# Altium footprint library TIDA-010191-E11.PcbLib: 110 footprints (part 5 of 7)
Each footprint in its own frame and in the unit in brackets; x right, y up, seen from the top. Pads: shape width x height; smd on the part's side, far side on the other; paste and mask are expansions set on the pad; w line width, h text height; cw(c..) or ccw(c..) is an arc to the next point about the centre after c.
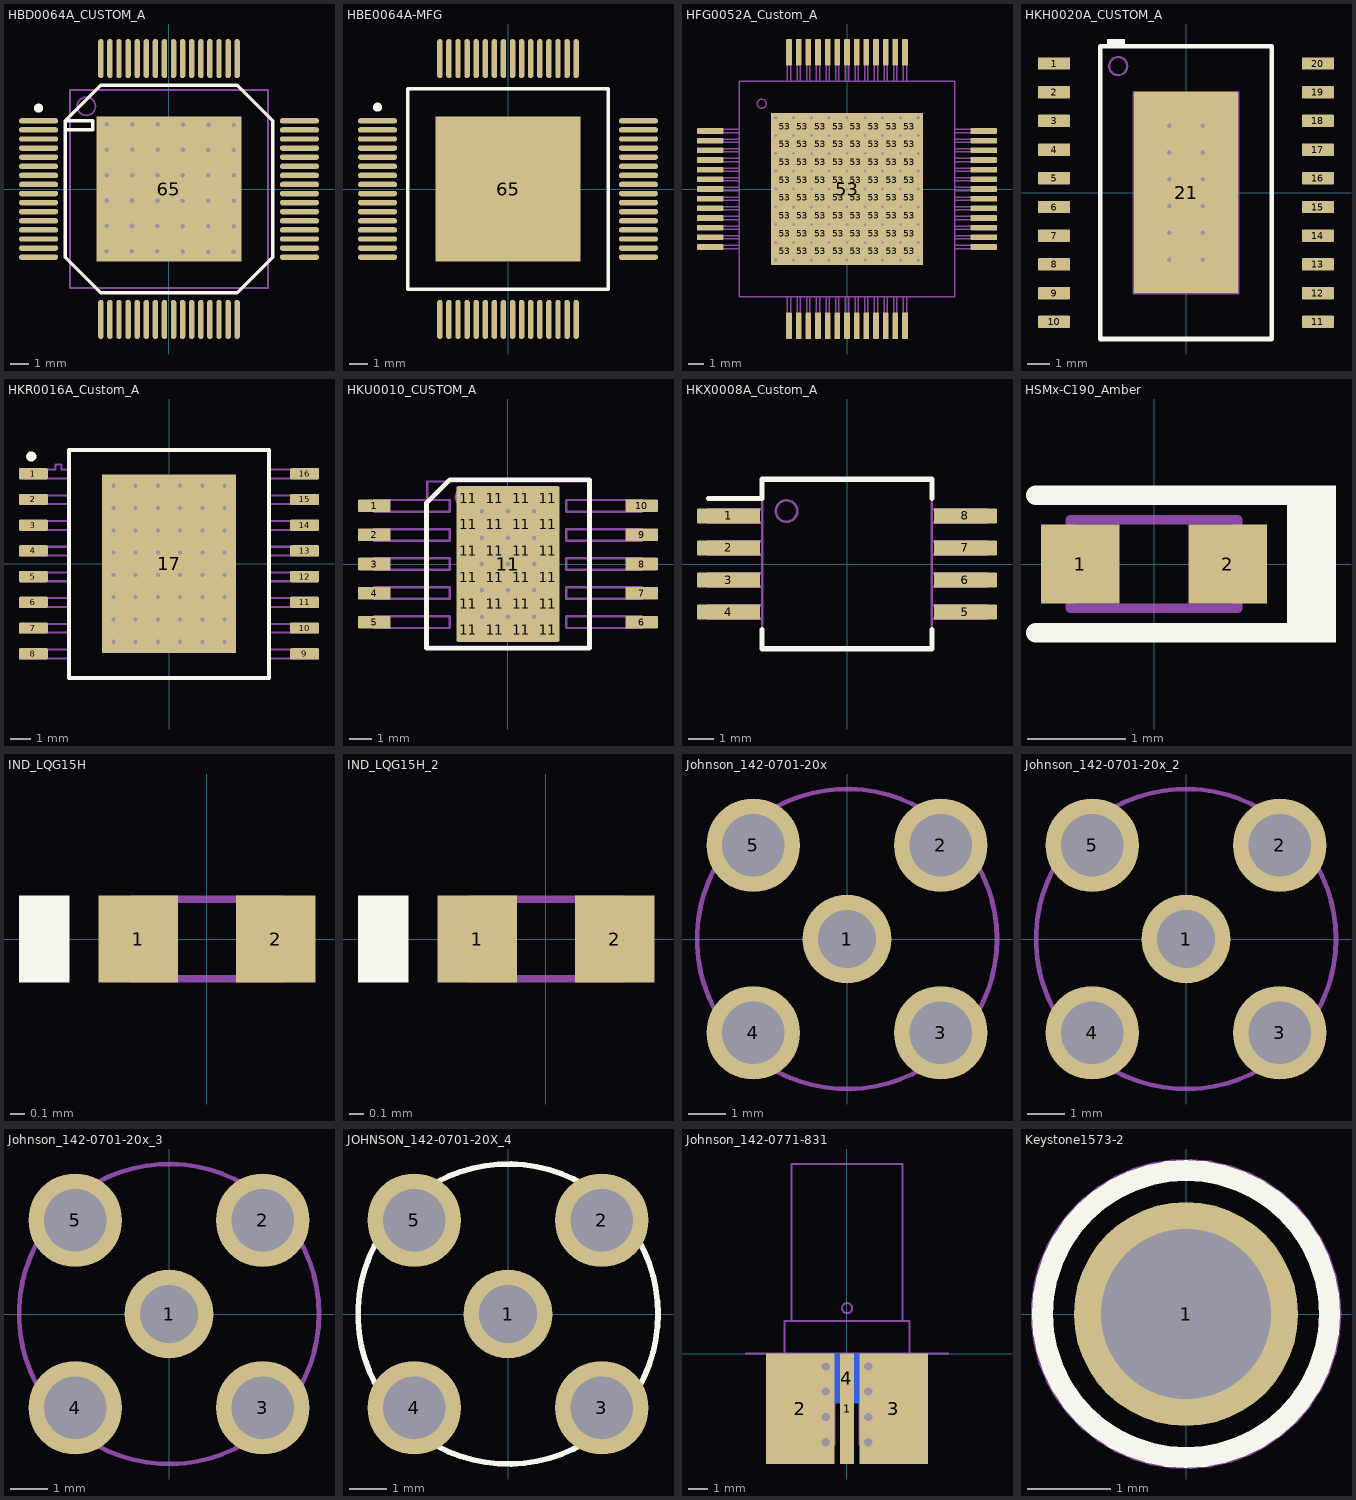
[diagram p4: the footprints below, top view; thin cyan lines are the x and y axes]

## HBD0064A_CUSTOM_A [mm] "CFP, 64-Leads, Body 10.9x10.9mm, Pitch 0.5 mm"
height 2.31
pads (65):
  rrect100% 2.15x0.3 smd: 1(-7.175,3.75) 2(-7.175,3.25) 3(-7.175,2.75) 4(-7.175,2.25) 5(-7.175,1.75) 6(-7.175,1.25) 7(-7.175,0.75) 8(-7.175,0.25) 9(-7.175,-0.25) 10(-7.175,-0.75) 11(-7.175,-1.25) 12(-7.175,-1.75) 13(-7.175,-2.25) 14(-7.175,-2.75) 15(-7.175,-3.25) 16(-7.175,-3.75) 33(7.175,-3.75) 34(7.175,-3.25) 35(7.175,-2.75) 36(7.175,-2.25) 37(7.175,-1.75) 38(7.175,-1.25) 39(7.175,-0.75) 40(7.175,-0.25) 41(7.175,0.25) 42(7.175,0.75) 43(7.175,1.25) 44(7.175,1.75) 45(7.175,2.25) 46(7.175,2.75) 47(7.175,3.25) 48(7.175,3.75)
  rrect100% 0.3x2.15 smd: 17(-3.75,-7.175) 18(-3.25,-7.175) 19(-2.75,-7.175) 20(-2.25,-7.175) 21(-1.75,-7.175) 22(-1.25,-7.175) 23(-0.75,-7.175) 24(-0.25,-7.175) 25(0.25,-7.175) 26(0.75,-7.175) 27(1.25,-7.175) 28(1.75,-7.175) 29(2.25,-7.175) 30(2.75,-7.175) 31(3.25,-7.175) 32(3.75,-7.175) 49(3.75,7.175) 50(3.25,7.175) 51(2.75,7.175) 52(2.25,7.175) 53(1.75,7.175) 54(1.25,7.175) 55(0.75,7.175) 56(0.25,7.175) 57(-0.25,7.175) 58(-0.75,7.175) 59(-1.25,7.175) 60(-1.75,7.175) 61(-2.25,7.175) 62(-2.75,7.175) 63(-3.25,7.175) 64(-3.75,7.175)
  rrect1% 8x8 smd: 65(0,0)
via -3.417,3.56 diameter 0.508 hole 0.254
via -2.02,3.556 diameter 0.508 hole 0.254
via -0.623,3.552 diameter 0.508 hole 0.254
via 0.774,3.548 diameter 0.508 hole 0.254
via 2.171,3.544 diameter 0.508 hole 0.254
via 3.568,3.54 diameter 0.508 hole 0.254
via 3.56,0.746 diameter 0.508 hole 0.254
via 3.564,2.143 diameter 0.508 hole 0.254
via 3.552,-2.048 diameter 0.508 hole 0.254
via 3.548,-3.445 diameter 0.508 hole 0.254
via 2.163,0.75 diameter 0.508 hole 0.254
via 2.167,2.147 diameter 0.508 hole 0.254
via 2.155,-2.044 diameter 0.508 hole 0.254
via 2.151,-3.441 diameter 0.508 hole 0.254
via 0.766,0.754 diameter 0.508 hole 0.254
via 0.77,2.151 diameter 0.508 hole 0.254
via 0.758,-2.04 diameter 0.508 hole 0.254
via 0.754,-3.437 diameter 0.508 hole 0.254
via -0.631,0.758 diameter 0.508 hole 0.254
via -0.627,2.155 diameter 0.508 hole 0.254
via -0.639,-2.036 diameter 0.508 hole 0.254
via -0.643,-3.433 diameter 0.508 hole 0.254
via -2.028,0.762 diameter 0.508 hole 0.254
via -2.024,2.159 diameter 0.508 hole 0.254
via -2.036,-2.032 diameter 0.508 hole 0.254
via -2.04,-3.429 diameter 0.508 hole 0.254
via -3.437,-3.425 diameter 0.508 hole 0.254
via -3.433,-2.028 diameter 0.508 hole 0.254
via -3.421,2.163 diameter 0.508 hole 0.254
via -3.425,0.766 diameter 0.508 hole 0.254
via 3.556,-0.651 diameter 0.508 hole 0.254
via 2.159,-0.647 diameter 0.508 hole 0.254
via 0.762,-0.643 diameter 0.508 hole 0.254
via -3.429,-0.631 diameter 0.508 hole 0.254
via -2.032,-0.635 diameter 0.508 hole 0.254
via -0.635,-0.639 diameter 0.508 hole 0.254
Top Overlay:
  circle w0.25: c-7.175,4.45 r0.125
  lines w0.2: -5.7,3.25 -4.2,3.25 -4.2,3.75 -5.7,3.75 ; -5.7,3.75 -5.7,-3.75 -3.75,-5.7 3.75,-5.7 5.7,-3.75 5.7,3.75 3.75,5.7 -3.75,5.7 -5.7,3.75
Mechanical 5:
  circle w0.1: c-4.55,4.55 r0.5
  lines w0.1: -5.45,-5.45 -5.45,5.45 5.45,5.45 5.45,-5.45 -5.45,-5.45
  text ".Designator" at -2,-0.7 h1.85
3D body "CQFP50P1560X1560X231-64N.step": height 2.31, standoff 0, extent -7.865,-7.865 7.865,7.865

## HBE0064A-MFG [mm]
pads (65):
  rrect100% 2.15x0.3 smd paste+0 mask+0: 1(-7.175,3.75) 2(-7.175,3.25) 3(-7.175,2.75) 4(-7.175,2.25) 5(-7.175,1.75) 6(-7.175,1.25) 7(-7.175,0.75) 8(-7.175,0.25) 9(-7.175,-0.25) 10(-7.175,-0.75) 11(-7.175,-1.25) 12(-7.175,-1.75) 13(-7.175,-2.25) 14(-7.175,-2.75) 15(-7.175,-3.25) 16(-7.175,-3.75) 33(7.175,-3.75) 34(7.175,-3.25) 35(7.175,-2.75) 36(7.175,-2.25) 37(7.175,-1.75) 38(7.175,-1.25) 39(7.175,-0.75) 40(7.175,-0.25) 41(7.175,0.25) 42(7.175,0.75) 43(7.175,1.25) 44(7.175,1.75) 45(7.175,2.25) 46(7.175,2.75) 47(7.175,3.25) 48(7.175,3.75)
  rrect100% 0.3x2.15 smd paste+0 mask+0: 17(-3.75,-7.175) 18(-3.25,-7.175) 19(-2.75,-7.175) 20(-2.25,-7.175) 21(-1.75,-7.175) 22(-1.25,-7.175) 23(-0.75,-7.175) 24(-0.25,-7.175) 25(0.25,-7.175) 26(0.75,-7.175) 27(1.25,-7.175) 28(1.75,-7.175) 29(2.25,-7.175) 30(2.75,-7.175) 31(3.25,-7.175) 32(3.75,-7.175) 49(3.75,7.175) 50(3.25,7.175) 51(2.75,7.175) 52(2.25,7.175) 53(1.75,7.175) 54(1.25,7.175) 55(0.75,7.175) 56(0.25,7.175) 57(-0.25,7.175) 58(-0.75,7.175) 59(-1.25,7.175) 60(-1.75,7.175) 61(-2.25,7.175) 62(-2.75,7.175) 63(-3.25,7.175) 64(-3.75,7.175)
  rrect1% 8x8 smd paste+0 mask+0: 65(0,0)
Top Overlay:
  circle w0.25: c-7.175,4.5 r0.125
  lines w0.2: -5.515,-5.515 5.515,-5.515 5.515,5.515 -5.515,5.515 -5.515,-5.515
Mechanical 5:
  lines w0.1: -5.515,-5.515 5.515,-5.515 5.515,5.515 -5.515,5.515 -5.515,-5.515
  text ".Designator" at 0,0 h0.5
3D body "IC_LMK04832W-MLS_CFP64.STEP": height 0.25, standoff 0, extent -8.35,-8.35 8.35,8.35

## HFG0052A_Custom_A [mm] "CFP-52"
height 2.68
pads (117):
  rrect26% 1.727x0.381 smd: 1(-8.992,3.81) 2(-8.992,3.175) 3(-8.992,2.54) 4(-8.992,1.905) 5(-8.992,1.27) 6(-8.992,0.635) 7(-8.992,0) 8(-8.992,-0.635) 9(-8.992,-1.27) 10(-8.992,-1.905) 11(-8.992,-2.54) 12(-8.992,-3.175) 13(-8.992,-3.81) 27(8.992,-3.81) 28(8.992,-3.175) 29(8.992,-2.54) 30(8.992,-1.905) 31(8.992,-1.27) 32(8.992,-0.635) 33(8.992,0) 34(8.992,0.635) 35(8.992,1.27) 36(8.992,1.905) 37(8.992,2.54) 38(8.992,3.175) 39(8.992,3.81)
  rrect26% 0.381x1.727 smd: 14(-3.81,-8.992) 15(-3.175,-8.992) 16(-2.54,-8.992) 17(-1.905,-8.992) 18(-1.27,-8.992) 19(-0.635,-8.992) 20(0,-8.992) 21(0.635,-8.992) 22(1.27,-8.992) 23(1.905,-8.992) 24(2.54,-8.992) 25(3.175,-8.992) 26(3.81,-8.992) 40(3.81,8.992) 41(3.175,8.992) 42(2.54,8.992) 43(1.905,8.992) 44(1.27,8.992) 45(0.635,8.992) 46(0,8.992) 47(-0.635,8.992) 48(-1.27,8.992) 49(-1.905,8.992) 50(-2.54,8.992) 51(-3.175,8.992) 52(-3.81,8.992)
  rrect50% 0.97x0.97 on Top Paste: 53(-4.095,-4.095) 53(-4.095,-2.925) 53(-4.095,-1.755) 53(-4.095,-0.585) 53(-4.095,0.585) 53(-4.095,1.755) 53(-4.095,2.925) 53(-4.095,4.095) 53(-2.925,-4.095) 53(-2.925,-2.925) 53(-2.925,-1.755) 53(-2.925,-0.585) 53(-2.925,0.585) 53(-2.925,1.755) 53(-2.925,2.925) 53(-2.925,4.095) 53(-1.755,-4.095) 53(-1.755,-2.925) 53(-1.755,-1.755) 53(-1.755,-0.585) 53(-1.755,0.585) 53(-1.755,1.755) 53(-1.755,2.925) 53(-1.755,4.095) 53(-0.585,-4.095) 53(-0.585,-2.925) 53(-0.585,-1.755) 53(-0.585,-0.585) 53(-0.585,0.585) 53(-0.585,1.755) 53(-0.585,2.925) 53(-0.585,4.095) 53(0.585,-4.095) 53(0.585,-2.925) 53(0.585,-1.755) 53(0.585,-0.585) 53(0.585,0.585) 53(0.585,1.755) 53(0.585,2.925) 53(0.585,4.095) 53(1.755,-4.095) 53(1.755,-2.925) 53(1.755,-1.755) 53(1.755,-0.585) 53(1.755,0.585) 53(1.755,1.755) 53(1.755,2.925) 53(1.755,4.095) 53(2.925,-4.095) 53(2.925,-2.925) 53(2.925,-1.755) 53(2.925,-0.585) 53(2.925,0.585) 53(2.925,1.755) 53(2.925,2.925) 53(2.925,4.095) 53(4.095,-4.095) 53(4.095,-2.925) 53(4.095,-1.755) 53(4.095,-0.585) 53(4.095,0.585) 53(4.095,1.755) 53(4.095,2.925) 53(4.095,4.095)
  rrect1% 10x10 smd paste-5: 53(0,0)
via -1.17,-1.17 diameter 0.5 hole 0.2
via -2.34,-1.17 diameter 0.5 hole 0.2
via -3.51,-1.17 diameter 0.5 hole 0.2
via -4.68,-1.17 diameter 0.5 hole 0.2
via 4.68,-1.17 diameter 0.5 hole 0.2
via 3.51,-1.17 diameter 0.5 hole 0.2
via 2.34,-1.17 diameter 0.5 hole 0.2
via 1.17,-1.17 diameter 0.5 hole 0.2
via 0,-1.17 diameter 0.5 hole 0.2
via -1.17,-2.34 diameter 0.5 hole 0.2
via -2.34,-2.34 diameter 0.5 hole 0.2
via -3.51,-2.34 diameter 0.5 hole 0.2
via -4.68,-2.34 diameter 0.5 hole 0.2
via 4.68,-2.34 diameter 0.5 hole 0.2
via 3.51,-2.34 diameter 0.5 hole 0.2
via 2.34,-2.34 diameter 0.5 hole 0.2
via 1.17,-2.34 diameter 0.5 hole 0.2
via 0,-2.34 diameter 0.5 hole 0.2
via -1.17,-3.51 diameter 0.5 hole 0.2
via -2.34,-3.51 diameter 0.5 hole 0.2
via -3.51,-3.51 diameter 0.5 hole 0.2
via -4.68,-3.51 diameter 0.5 hole 0.2
via 4.68,-3.51 diameter 0.5 hole 0.2
via 3.51,-3.51 diameter 0.5 hole 0.2
via 2.34,-3.51 diameter 0.5 hole 0.2
via 1.17,-3.51 diameter 0.5 hole 0.2
via 0,-3.51 diameter 0.5 hole 0.2
via -1.17,-4.68 diameter 0.5 hole 0.2
via -2.34,-4.68 diameter 0.5 hole 0.2
via -3.51,-4.68 diameter 0.5 hole 0.2
via -4.68,-4.68 diameter 0.5 hole 0.2
via 4.68,-4.68 diameter 0.5 hole 0.2
via 3.51,-4.68 diameter 0.5 hole 0.2
via 2.34,-4.68 diameter 0.5 hole 0.2
via 1.17,-4.68 diameter 0.5 hole 0.2
via 0,-4.68 diameter 0.5 hole 0.2
via 0,4.68 diameter 0.5 hole 0.2
via 1.17,4.68 diameter 0.5 hole 0.2
via 2.34,4.68 diameter 0.5 hole 0.2
via 3.51,4.68 diameter 0.5 hole 0.2
via 4.68,4.68 diameter 0.5 hole 0.2
via -4.68,4.68 diameter 0.5 hole 0.2
via -3.51,4.68 diameter 0.5 hole 0.2
via -2.34,4.68 diameter 0.5 hole 0.2
via -1.17,4.68 diameter 0.5 hole 0.2
via 0,3.51 diameter 0.5 hole 0.2
via 1.17,3.51 diameter 0.5 hole 0.2
via 2.34,3.51 diameter 0.5 hole 0.2
via 3.51,3.51 diameter 0.5 hole 0.2
via 4.68,3.51 diameter 0.5 hole 0.2
via -4.68,3.51 diameter 0.5 hole 0.2
via -3.51,3.51 diameter 0.5 hole 0.2
via -2.34,3.51 diameter 0.5 hole 0.2
via -1.17,3.51 diameter 0.5 hole 0.2
via 0,2.34 diameter 0.5 hole 0.2
via 1.17,2.34 diameter 0.5 hole 0.2
via 2.34,2.34 diameter 0.5 hole 0.2
via 3.51,2.34 diameter 0.5 hole 0.2
via 4.68,2.34 diameter 0.5 hole 0.2
via -4.68,2.34 diameter 0.5 hole 0.2
via -3.51,2.34 diameter 0.5 hole 0.2
via -2.34,2.34 diameter 0.5 hole 0.2
via -1.17,2.34 diameter 0.5 hole 0.2
via 0,1.17 diameter 0.5 hole 0.2
via 1.17,1.17 diameter 0.5 hole 0.2
via 2.34,1.17 diameter 0.5 hole 0.2
via 3.51,1.17 diameter 0.5 hole 0.2
via 4.68,1.17 diameter 0.5 hole 0.2
via -4.68,1.17 diameter 0.5 hole 0.2
via -3.51,1.17 diameter 0.5 hole 0.2
via -2.34,1.17 diameter 0.5 hole 0.2
via -1.17,1.17 diameter 0.5 hole 0.2
via -1.17,0 diameter 0.5 hole 0.2
via -2.34,0 diameter 0.5 hole 0.2
via -3.51,0 diameter 0.5 hole 0.2
via -4.68,0 diameter 0.5 hole 0.2
via 4.68,0 diameter 0.5 hole 0.2
via 3.51,0 diameter 0.5 hole 0.2
via 2.34,0 diameter 0.5 hole 0.2
via 1.17,0 diameter 0.5 hole 0.2
via 0,0 diameter 0.5 hole 0.2
Mechanical 5:
  drawing of 161 lines, arcs and shapes, not listed
  text ".Designator" at -1.854,-0.508 h1.02
3D body: height 0.2, standoff 0, extent 3.711,-9.599 3.909,-7.086
3D body: height 0.2, standoff 0, extent 3.076,-9.599 3.274,-7.086
3D body: height 0.2, standoff 0, extent 2.441,-9.599 2.639,-7.086
3D body: height 0.2, standoff 0, extent 1.806,-9.599 2.004,-7.086
3D body: height 0.2, standoff 0, extent 1.171,-9.599 1.369,-7.086
3D body: height 0.2, standoff 0, extent 0.536,-9.599 0.734,-7.086
3D body: height 0.2, standoff 0, extent -0.099,-9.599 0.099,-7.086
3D body: height 0.2, standoff 0, extent -0.734,-9.599 -0.536,-7.086
3D body: height 0.2, standoff 0, extent -1.369,-9.599 -1.171,-7.086
3D body: height 0.2, standoff 0, extent -2.004,-9.599 -1.806,-7.086
3D body: height 0.2, standoff 0, extent -2.639,-9.599 -2.441,-7.086
3D body: height 0.2, standoff 0, extent -3.274,-9.599 -3.076,-7.086
3D body: height 0.2, standoff 0, extent -3.909,-9.599 -3.711,-7.086
3D body: height 0.2, standoff 0, extent -3.909,7.086 -3.711,9.599
3D body: height 0.2, standoff 0, extent -3.274,7.086 -3.076,9.599
3D body: height 0.2, standoff 0, extent -2.639,7.086 -2.441,9.599
3D body: height 0.2, standoff 0, extent -2.004,7.086 -1.806,9.599
3D body: height 0.2, standoff 0, extent -1.369,7.086 -1.171,9.599
3D body: height 0.2, standoff 0, extent -0.734,7.086 -0.536,9.599
3D body: height 0.2, standoff 0, extent -0.099,7.086 0.099,9.599
3D body: height 0.2, standoff 0, extent 0.536,7.086 0.734,9.599
3D body: height 0.2, standoff 0, extent 1.171,7.086 1.369,9.599
3D body: height 0.2, standoff 0, extent 1.806,7.086 2.004,9.599
3D body: height 0.2, standoff 0, extent 2.441,7.086 2.639,9.599
3D body: height 0.2, standoff 0, extent 3.076,7.086 3.274,9.599
3D body: height 0.2, standoff 0, extent 3.711,7.086 3.909,9.599
3D body: height 0.2, standoff 0, extent 7.086,-3.909 9.599,-3.711
3D body: height 0.2, standoff 0, extent 7.086,-3.274 9.599,-3.076
3D body: height 0.2, standoff 0, extent 7.086,-2.639 9.599,-2.441
3D body: height 0.2, standoff 0, extent 7.086,-2.004 9.599,-1.806
3D body: height 0.2, standoff 0, extent 7.086,-1.369 9.599,-1.171
3D body: height 0.2, standoff 0, extent 7.086,-0.734 9.599,-0.536
3D body: height 0.2, standoff 0, extent 7.086,-0.099 9.599,0.099
3D body: height 0.2, standoff 0, extent 7.086,0.536 9.599,0.734
3D body: height 0.2, standoff 0, extent 7.086,1.171 9.599,1.369
3D body: height 0.2, standoff 0, extent 7.086,1.806 9.599,2.004
3D body: height 0.2, standoff 0, extent 7.086,2.441 9.599,2.639
3D body: height 0.2, standoff 0, extent 7.086,3.076 9.599,3.274
3D body: height 0.2, standoff 0, extent 7.086,3.711 9.599,3.909
3D body: height 0.2, standoff 0, extent -9.599,3.711 -7.086,3.909
3D body: height 0.2, standoff 0, extent -9.599,3.076 -7.086,3.274
3D body: height 0.2, standoff 0, extent -9.599,2.441 -7.086,2.639
3D body: height 0.2, standoff 0, extent -9.599,1.806 -7.086,2.004
3D body: height 0.2, standoff 0, extent -9.599,1.171 -7.086,1.369
3D body: height 0.2, standoff 0, extent -9.599,0.536 -7.086,0.734
3D body: height 0.2, standoff 0, extent -9.599,-0.099 -7.086,0.099
3D body: height 0.2, standoff 0, extent -9.599,-0.734 -7.086,-0.536
3D body: height 0.2, standoff 0, extent -9.599,-1.369 -7.086,-1.171
3D body: height 0.2, standoff 0, extent -9.599,-2.004 -7.086,-1.806
3D body: height 0.2, standoff 0, extent -9.599,-2.639 -7.086,-2.441
3D body: height 0.2, standoff 0, extent -9.599,-3.274 -7.086,-3.076
3D body: height 0.2, standoff 0, extent -9.599,-3.909 -7.086,-3.711
3D body: height 2.68, standoff 2, extent -4.999,-4.999 4.999,4.999
3D body: height 2, standoff 0, extent -7.084,-7.084 7.084,7.084

## HKH0020A_CUSTOM_A [mm] "SMD, 20-Leads, Body 12.7x7.38mm, Pitch 1.27mm"
height 2.23
pads (21):
  rrect18% 1.42x0.55 smd: 1(-5.84,5.715) 2(-5.84,4.445) 3(-5.84,3.175) 4(-5.84,1.905) 5(-5.84,0.635) 6(-5.84,-0.635) 7(-5.84,-1.905) 8(-5.84,-3.175) 9(-5.84,-4.445) 10(-5.84,-5.715) 11(5.84,-5.715) 12(5.84,-4.445) 13(5.84,-3.175) 14(5.84,-1.905) 15(5.84,-0.635) 16(5.84,0.635) 17(5.84,1.905) 18(5.84,3.175) 19(5.84,4.445) 20(5.84,5.715)
  rrect2% 4.62x8.89 smd paste-8: 21(0,0)
via -0.74,-2.963 diameter 0.5 hole 0.2
via 0.74,-2.963 diameter 0.5 hole 0.2
via -0.74,-1.777 diameter 0.5 hole 0.2
via 0.74,-1.777 diameter 0.5 hole 0.2
via -0.74,-0.592 diameter 0.5 hole 0.2
via 0.74,-0.592 diameter 0.5 hole 0.2
via -0.74,0.593 diameter 0.5 hole 0.2
via 0.74,0.593 diameter 0.5 hole 0.2
via -0.74,1.778 diameter 0.5 hole 0.2
via 0.74,1.778 diameter 0.5 hole 0.2
via 0.74,2.963 diameter 0.5 hole 0.2
via -0.74,2.963 diameter 0.5 hole 0.2
Top Overlay:
  rectangle: -3.5,6.5 -2.7,6.8
  lines w0.2: -3.8,-6.475 3.8,-6.475 3.8,6.475 -3.8,6.475 -3.8,-6.475
Top Paste:
  region: 2.119,2.863 0.84,2.863 0.84,1.878 2.119,1.878
  rectangle: -2.118,1.878 -0.839,2.863
  rectangle: -0.639,1.877 0.64,2.862
  region: 2.119,4.047 0.84,4.047 0.84,3.062 2.119,3.062
  rectangle: -2.119,3.063 -0.84,4.048
  rectangle: -0.639,3.062 0.64,4.047
  rectangle: -0.64,-4.047 0.639,-3.062
  rectangle: -2.118,-4.047 -0.839,-3.062
  region: 2.118,-3.062 0.839,-3.062 0.839,-4.047 2.118,-4.047
  rectangle: -0.64,-2.862 0.639,-1.877
  rectangle: -2.118,-2.862 -0.839,-1.877
  region: 2.119,-1.877 0.84,-1.877 0.84,-2.862 2.119,-2.862
  rectangle: -0.639,-1.677 0.64,-0.692
  rectangle: -2.118,-1.677 -0.839,-0.692
  region: 2.118,-0.692 0.839,-0.692 0.839,-1.677 2.118,-1.677
  rectangle: -0.64,0.692 0.64,1.677
  rectangle: -2.118,0.692 -0.839,1.677
  region: 2.118,1.677 0.839,1.677 0.839,0.692 2.118,0.692
  region: 2.119,0.493 0.84,0.493 0.84,-0.492 2.119,-0.492
  rectangle: -2.118,-0.492 -0.839,0.493
  rectangle: -0.639,-0.492 0.64,0.493
Mechanical 5:
  circle w0.1: c-3,5.6 r0.4
  lines w0.1: -3.8,-6.475 -3.8,6.475 3.8,6.475 3.8,-6.475 -3.8,-6.475 ; -2.31,-4.445 2.31,-4.445 2.31,4.445 -2.31,4.445 -2.31,-4.445
  text ".Designator" at -1.524,-0.508 h1.02
3D body: height 1.23, standoff 0.1, extent -2.31,-4.445 2.31,4.445
3D body: height 2.23, standoff 1.23, extent -3.8,-6.475 3.8,6.475
3D body: height 2.23, standoff 2.23, extent -3.399,5.201 -2.601,5.999
3D body: height 1.23, standoff 0, extent -6.475,5.49 -3.274,5.94
3D body: height 1.23, standoff 0, extent -6.475,4.22 -3.274,4.67
3D body: height 1.23, standoff 0, extent -6.475,2.95 -3.274,3.4
3D body: height 1.23, standoff 0, extent -6.475,1.68 -3.274,2.13
3D body: height 1.23, standoff 0, extent -6.475,0.41 -3.274,0.86
3D body: height 1.23, standoff 0, extent -6.475,-0.86 -3.274,-0.41
3D body: height 1.23, standoff 0, extent -6.475,-2.13 -3.274,-1.68
3D body: height 1.23, standoff 0, extent -6.475,-3.4 -3.274,-2.95
3D body: height 1.23, standoff 0, extent -6.475,-4.67 -3.274,-4.22
3D body: height 1.23, standoff 0, extent -6.475,-5.94 -3.274,-5.49
3D body: height 1.23, standoff 0, extent 3.274,5.49 6.475,5.94
3D body: height 1.23, standoff 0, extent 3.274,4.22 6.475,4.67
3D body: height 1.23, standoff 0, extent 3.274,2.95 6.475,3.4
3D body: height 1.23, standoff 0, extent 3.274,1.68 6.475,2.13
3D body: height 1.23, standoff 0, extent 3.274,0.41 6.475,0.86
3D body: height 1.23, standoff 0, extent 3.274,-0.86 6.475,-0.41
3D body: height 1.23, standoff 0, extent 3.274,-3.4 6.475,-2.95
3D body: height 1.23, standoff 0, extent 3.274,-4.67 6.475,-4.22
3D body: height 1.23, standoff 0, extent 3.274,-5.94 6.475,-5.49
3D body: height 1.23, standoff 0, extent 3.274,-2.13 6.475,-1.68

## HKR0016A_Custom_A [mil] "16-Leads, Body 11.3x9.9mm, Pitch 1.27mm, Thermal Pad 9x6.78mm"
height 118.9
pads (17):
  rrect25% 56x22 smd: 1(-263.5,175) 2(-263.5,125) 3(-263.5,75) 4(-263.5,25) 5(-263.5,-25) 6(-263.5,-75) 7(-263.5,-125) 8(-263.5,-175) 9(263.5,-175) 10(263.5,-125) 11(263.5,-75) 12(263.5,-25) 13(263.5,25) 14(263.5,75) 15(263.5,125) 16(263.5,175)
  rect 259.45x346.46 smd: 17(0,0)
via -108.27,151.57 diameter 19.68 hole 7.87
via -64.96,151.57 diameter 19.68 hole 7.87
via -21.65,151.57 diameter 19.68 hole 7.87
via 21.65,151.57 diameter 19.68 hole 7.87
via 64.96,151.57 diameter 19.68 hole 7.87
via 108.27,151.57 diameter 19.68 hole 7.87
via -108.27,108.27 diameter 19.68 hole 7.87
via -64.96,108.27 diameter 19.68 hole 7.87
via -21.65,108.27 diameter 19.68 hole 7.87
via 21.65,108.27 diameter 19.68 hole 7.87
via 64.96,108.27 diameter 19.68 hole 7.87
via 108.27,108.27 diameter 19.68 hole 7.87
via -108.27,64.96 diameter 19.68 hole 7.87
via -64.96,64.96 diameter 19.68 hole 7.87
via -21.65,64.96 diameter 19.68 hole 7.87
via 21.65,64.96 diameter 19.68 hole 7.87
via 64.96,64.96 diameter 19.68 hole 7.87
via 108.27,64.96 diameter 19.68 hole 7.87
via -108.27,21.65 diameter 19.68 hole 7.87
via -64.96,21.65 diameter 19.68 hole 7.87
via -21.65,21.65 diameter 19.68 hole 7.87
via 21.65,21.65 diameter 19.68 hole 7.87
via 64.96,21.65 diameter 19.68 hole 7.87
via 108.27,21.65 diameter 19.68 hole 7.87
via -108.27,-21.65 diameter 19.68 hole 7.87
via -64.96,-21.65 diameter 19.68 hole 7.87
via -21.65,-21.65 diameter 19.68 hole 7.87
via 21.65,-21.65 diameter 19.68 hole 7.87
via 64.96,-21.65 diameter 19.68 hole 7.87
via 108.27,-21.65 diameter 19.68 hole 7.87
via -108.27,-64.96 diameter 19.68 hole 7.87
via -64.96,-64.96 diameter 19.68 hole 7.87
via -21.65,-64.96 diameter 19.68 hole 7.87
via 21.65,-64.96 diameter 19.68 hole 7.87
via 64.96,-64.96 diameter 19.68 hole 7.87
via 108.27,-64.96 diameter 19.68 hole 7.87
via -108.27,-108.27 diameter 19.68 hole 7.87
via -64.96,-108.27 diameter 19.68 hole 7.87
via -21.65,-108.27 diameter 19.68 hole 7.87
via 21.65,-108.27 diameter 19.68 hole 7.87
via 64.96,-108.27 diameter 19.68 hole 7.87
via 108.27,-108.27 diameter 19.68 hole 7.87
via -108.27,-151.57 diameter 19.68 hole 7.87
via -64.96,-151.57 diameter 19.68 hole 7.87
via -21.65,-151.57 diameter 19.68 hole 7.87
via 21.65,-151.57 diameter 19.68 hole 7.87
via 64.96,-151.57 diameter 19.68 hole 7.87
via 108.27,-151.57 diameter 19.68 hole 7.87
Top Overlay:
  circle w9.84: c-267.72,208.46 r4.92
  lines w7.87: -194.49,-222.15 194.49,-222.15 194.49,221.15 -194.49,221.15 -194.49,-222.15
Mechanical 5:
  drawing of 168 lines, arcs and shapes, not listed
  text "1" at -168,158 h40
  text ".Designator" at -72,-19 h40
3D body "HKR0016_Custom_A.stp": height 91.85, standoff 0, extent -290,-221.65 290,221.66

## HKU0010_CUSTOM_A [mm] "HKU custom footprint"
height 2.593
pads (35):
  rrect18% 1.42x0.55 smd: 1(-5.84,2.54) 2(-5.84,1.27) 3(-5.84,0) 4(-5.84,-1.27) 5(-5.84,-2.54) 6(5.84,-2.54) 7(5.84,-1.27) 8(5.84,0) 9(5.84,1.27) 10(5.84,2.54)
  rrect50% 0.95x0.95 on Top Paste: 11(-1.725,-2.875) 11(-1.725,-1.725) 11(-1.725,-0.575) 11(-1.725,0.575) 11(-1.725,1.725) 11(-1.725,2.875) 11(-0.575,-2.875) 11(-0.575,-1.725) 11(-0.575,-0.575) 11(-0.575,0.575) 11(-0.575,1.725) 11(-0.575,2.875) 11(0.575,-2.875) 11(0.575,-1.725) 11(0.575,-0.575) 11(0.575,0.575) 11(0.575,1.725) 11(0.575,2.875) 11(1.725,-2.875) 11(1.725,-1.725) 11(1.725,-0.575) 11(1.725,0.575) 11(1.725,1.725) 11(1.725,2.875)
  rrect4% 4.5x6.82 smd paste-3 mask-0.05: 11(0,0)
via -1.15,-1.15 diameter 0.5 hole 0.2
via 1.15,-1.15 diameter 0.5 hole 0.2
via 0,-1.15 diameter 0.5 hole 0.2
via -1.15,-2.3 diameter 0.5 hole 0.2
via 1.15,-2.3 diameter 0.5 hole 0.2
via 0,-2.3 diameter 0.5 hole 0.2
via 0,2.3 diameter 0.5 hole 0.2
via 1.15,2.3 diameter 0.5 hole 0.2
via -1.15,2.3 diameter 0.5 hole 0.2
via 0,1.15 diameter 0.5 hole 0.2
via 1.15,1.15 diameter 0.5 hole 0.2
via -1.15,1.15 diameter 0.5 hole 0.2
via -1.15,0 diameter 0.5 hole 0.2
via 1.15,0 diameter 0.5 hole 0.2
via 0,0 diameter 0.5 hole 0.2
Top Overlay:
  lines w0.203: -3.556,-3.683 -3.556,2.667 -2.54,3.683 3.556,3.683 3.556,-3.683 -3.556,-3.683
Mechanical 5:
  circle w0.102: c-1.905,2.921 r0.381
  lines w0.1: -3.52,-3.6 3.52,-3.6 3.52,3.6 -3.52,3.6 -3.52,-3.6
  lines w0.102: -5.842,-2.794 -5.842,-2.286 -2.54,-2.286 -2.54,-2.794 -5.842,-2.794 ; -5.842,-1.524 -2.54,-1.524 -2.54,-1.016 -5.842,-1.016 -5.842,-1.524 ; -5.842,-0.254 -2.54,-0.254 -2.54,0.254 -5.842,0.254 -5.842,-0.254 ; -5.842,1.016 -2.54,1.016 -2.54,1.524 -5.842,1.524 -5.842,1.016 ; -5.842,2.286 -2.54,2.286 -2.54,2.794 -5.842,2.794 -5.842,2.286 ; 2.54,-2.794 2.54,-2.286 5.842,-2.286 5.842,-2.794 2.54,-2.794 ; 2.54,-1.524 2.54,-1.016 5.842,-1.016 5.842,-1.524 2.54,-1.524 ; 2.54,-0.254 2.54,0.254 5.842,0.254 5.842,-0.254 2.54,-0.254 ; 2.54,1.016 2.54,1.524 5.842,1.524 5.842,1.016 2.54,1.016 ; 2.54,2.286 2.54,2.794 5.842,2.794 5.842,2.286 2.54,2.286
  text ".Designator" at -2.032,-0.508 h1.02
3D body: height 0.95, standoff 0, extent -2.439,-3.599 2.439,3.599
3D body: height 2.59, standoff 0.95, extent -3.519,-3.599 3.519,3.599
3D body: height 0.94, standoff 0, extent -5.841,-2.793 -3.521,-2.287
3D body: height 0.94, standoff 0, extent -5.841,-1.523 -3.521,-1.017
3D body: height 0.94, standoff 0, extent -5.841,-0.253 -3.521,0.253
3D body: height 0.94, standoff 0, extent -5.841,1.017 -3.521,1.523
3D body: height 0.94, standoff 0, extent -5.841,2.287 -3.521,2.793
3D body: height 0.94, standoff 0, extent 3.521,-2.793 5.841,-2.287
3D body: height 0.94, standoff 0, extent 3.521,-1.523 5.841,-1.017
3D body: height 0.94, standoff 0, extent 3.521,-0.253 5.841,0.253
3D body: height 0.94, standoff 0, extent 3.521,1.017 5.841,1.523
3D body: height 0.94, standoff 0, extent 3.521,2.287 5.841,2.793
3D body: height 2.59, standoff 1.27, extent -2.285,2.541 -1.525,3.301

## HKX0008A_Custom_A [mm] "CFP, 8-Leads, Body 6.475x6.485mm, Pitch 1.27mm"
height 2.8
pads (8):
  rrect17% 2.5x0.6 smd: 1(-4.7,1.905) 2(-4.7,0.635) 3(-4.7,-0.635) 4(-4.7,-1.905) 5(4.7,-1.905) 6(4.7,-0.635) 7(4.7,0.635) 8(4.7,1.905)
Top Overlay:
  lines w0.2: -5.5,2.596 -3.367,2.596 -3.367,3.363 3.367,3.363 3.367,2.596 ; -3.367,-2.596 -3.367,-3.363 3.367,-3.363 3.367,-2.596
Mechanical 5:
  circle w0.1: c-2.4,2.1 r0.424
  lines w0.1: -3.368,-2.165 -5.54,-2.165 -5.54,-1.645 -3.368,-1.645 ; -3.368,-0.895 -5.54,-0.895 -5.54,-0.375 -3.368,-0.375 ; -3.368,0.375 -5.54,0.375 -5.54,0.895 -3.368,0.895 ; -3.368,1.645 -5.54,1.645 -5.54,2.165 -3.368,2.165 ; 3.368,-2.165 5.54,-2.165 5.54,-1.645 3.368,-1.645 ; 3.368,-0.895 5.54,-0.895 5.54,-0.375 3.368,-0.375 ; 3.368,0.375 5.54,0.375 5.54,0.895 3.368,0.895 ; 3.368,1.645 5.54,1.645 5.54,2.165 3.368,2.165 ; -3.367,-3.363 -3.367,3.363 3.367,3.363 3.367,-3.363 -3.367,-3.363
  text ".Designator" at -1.7,-0.4 h1
3D body "HKX0008A_NoLeads.stp": height 2.51, standoff 0.01, extent -3.253,-3.238 3.252,3.237

## HSMx-C190_Amber [mm] "SMD, 2-Leads, Body 1.6x0.8mm"
height 0.9
pads (2):
  rect 0.8x0.8 smd: 1(-0.75,0) 2(0.75,0)
Top Overlay:
  rectangle: 1.35,-0.8 1.85,0.8
  lines w0.2: -1.2,-0.7 1.4,-0.7 ; -1.2,0.7 1.4,0.7
Mechanical 5:
  region: 0.6,0.3 0.7,0.2 0.6,0.1
  lines w0.1: -0.85,-0.45 0.85,-0.45 0.85,-0.15 cw(c0.85,0) 0.85,0.15 0.85,0.45 -0.85,0.45 -0.85,0.15 cw(c-0.85,0) -0.85,-0.15 -0.85,-0.45
  text ".Designator" at -0.6,-0.2 h0.6
3D body "HSMA-C190.stp": height 0.9, standoff 0, extent -0.85,-0.45 0.85,0.45

## IND_LQG15H [mm] "MuRata"
height 0.55
pads (2):
  rect 0.55x0.6 smd: 1(-0.475,0) 2(0.475,0)
Top Overlay:
  rectangle: -1.3,-0.3 -0.95,0.3
Mechanical 5:
  rectangle: -0.7,-0.276 -0.525,0.274
  lines w0.05: -0.525,-0.275 -0.525,0.275 0.525,0.275 0.525,-0.275 -0.525,-0.275
  text ".Designator" at -0.45,-0.125 h0.25
3D body: height 0.55, standoff 0.54, extent -0.274,-0.274 -0.001,0.275
3D body: height 0.55, standoff 0, extent 0.276,-0.274 0.524,0.274
3D body: height 0.54, standoff 0, extent -0.274,-0.274 0.274,0.275
3D body: height 0.55, standoff 0, extent -0.524,-0.274 -0.276,0.274

## IND_LQG15H_2 [mm]
pads (2):
  rect 0.55x0.6 smd: 1(-0.475,0) 2(0.475,0)
Top Overlay:
  rectangle: -1.3,-0.3 -0.95,0.3
Mechanical 5:
  rectangle: -0.7,-0.275 -0.525,0.275
  lines w0.05: -0.525,-0.275 -0.525,0.275 0.525,0.275 0.525,-0.275 -0.525,-0.275
  text ".Designator" at -0.45,-0.125 h0.25
3D body: height 0.55, standoff 0.54, extent -0.274,-0.274 -0.001,0.274
3D body: height 0.55, standoff 0, extent 0.276,-0.274 0.524,0.274
3D body: height 0.54, standoff 0, extent -0.274,-0.274 0.274,0.274
3D body: height 0.55, standoff 0, extent -0.524,-0.274 -0.276,0.274

## Johnson_142-0701-20x [mil] "Johnson Components recommended land pattern"
height 375
pads (5):
  round 95 hole 62: 1(0,0)
  round 100 hole 67: 2(100,100) 3(100,-100) 4(-100,-100) 5(-100,100)
Mechanical 5:
  circle w5: c0,0 r160
  text ".Designator" at -60,-30 h60
3D body "Emerson_142-0701-201.stp": height 375, standoff -155, extent -155.99,-155.8 156.01,155.8

## Johnson_142-0701-20x_2 [mil]
pads (5):
  round 95 hole 62: 1(0,0)
  round 100 hole 67: 2(100,100) 3(100,-100) 4(-100,-100) 5(-100,100)
Mechanical 5:
  circle w5: c0,0 r160
  text ".Designator" at -60,-30 h60
3D body "Emerson_142-0701-201.stp": height 375, standoff -155, extent -155.99,-155.8 156.01,155.8

## Johnson_142-0701-20x_3 [mil]
pads (5):
  round 95 hole 62: 1(0,0)
  round 100 hole 67: 2(100,100) 3(100,-100) 4(-100,-100) 5(-100,100)
Mechanical 5:
  circle w5: c0,0 r160
  text ".Designator" at -60,-30 h60
3D body "Emerson_142-0701-201.stp": height 375, standoff -155, extent -155.99,-155.8 156.01,155.8

## JOHNSON_142-0701-20X_4 [mil]
pads (5):
  round 95 hole 62: 1(0,0)
  round 100 hole 67: 2(100,100) 3(100,-100) 4(-100,-100) 5(-100,100)
Top Overlay:
  circle w6: c0,0 r160
Mechanical 5:
  circle w5: c0,0 r160
  text ".Designator" at 3.99,-16.9 h25
3D body "Emerson_142-0701-201.stp": height 375, standoff -155, extent -155.99,-155.8 156.01,155.8

## Johnson_142-0771-831 [mil] "JACK, SMA, 50 Ohm, Gold, Edge Mount"
height 123.5
pads (12):
  rect 28.5x218 smd: 1(0,-109)
  rect 135.75x218 smd: 2(-92.13,-109) 3(92.13,-109)
  rect 270x97.5 smd far side: 4(0,-48.75)
  round 16 hole 16: ""(-42,-175) ""(-42,-125) ""(-42,-75) ""(-42,-25) ""(42,-175) ""(42,-75) ""(42,-25) ""(42,-125)
Mechanical 1:
  lines w3.94: -200,0 200,0
Mechanical 5:
  circle w3.94: c0,90 r10
  lines w3.94: -110,65 -110,375 110,375 110,65 ; -79.36,0 -79.36,-179 ; -25,-65 25,-65 ; -25,-60 25,-60 ; -25,0 -25,-179 -79.36,-179 ; -7.5,0 -7.5,-22.5 ccw(c0,-22.5) 7.5,-22.5 7.5,0 ; 25,0 25,-179 79.36,-179 ; 79.36,0 79.36,-179 ; -114.35,-179 -79.36,-179 ; -114.35,-179 -114.35,0 114.34,0 114.34,-179 ; -114.35,-179 -123.5,-179 -123.5,65 123.5,65 123.5,-179 114.34,-179 ; 79.36,-179 114.34,-179
  text ".Designator" at -70.87,137.8 h40
3D body "142-0771-831.stp": height 130.9, standoff -116, extent -123.5,-179 123.47,375

## Keystone1573-2 [mm] "Double Turret"
height 4.7
pads (1):
  round 2.7 hole 2.05: 1(0,0)
Top Overlay:
  circle w0.254: c0,0 r1.727
Mechanical 5:
  circle w0.127: c0,0 r1.805
  text ".Designator" at -1.397,-0.381 h0.76
3D body "Keystone1573-2.stp": height 4.72, standoff -2.06, extent -1.18,-1.178 1.171,1.178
